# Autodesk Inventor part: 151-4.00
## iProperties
Created: 2007-06
Part Number: 151-4.00
Document SubType Name: Modeling
Designer: btaylor
Density: 1 g/cm^3
Author: btaylor
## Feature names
1. Sweep1
2. Extrusion1
3. Extrusion2
4. Extrusion3
5. Extrusion4
6. Fillet1
7. Fillet2
8. Hole1
9. Hole2
10. Sweep2
11. Fillet3
12. Fillet4
13. Chamfer1
14. Chamfer2
